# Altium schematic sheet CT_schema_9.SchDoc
size 250 x 169 mm
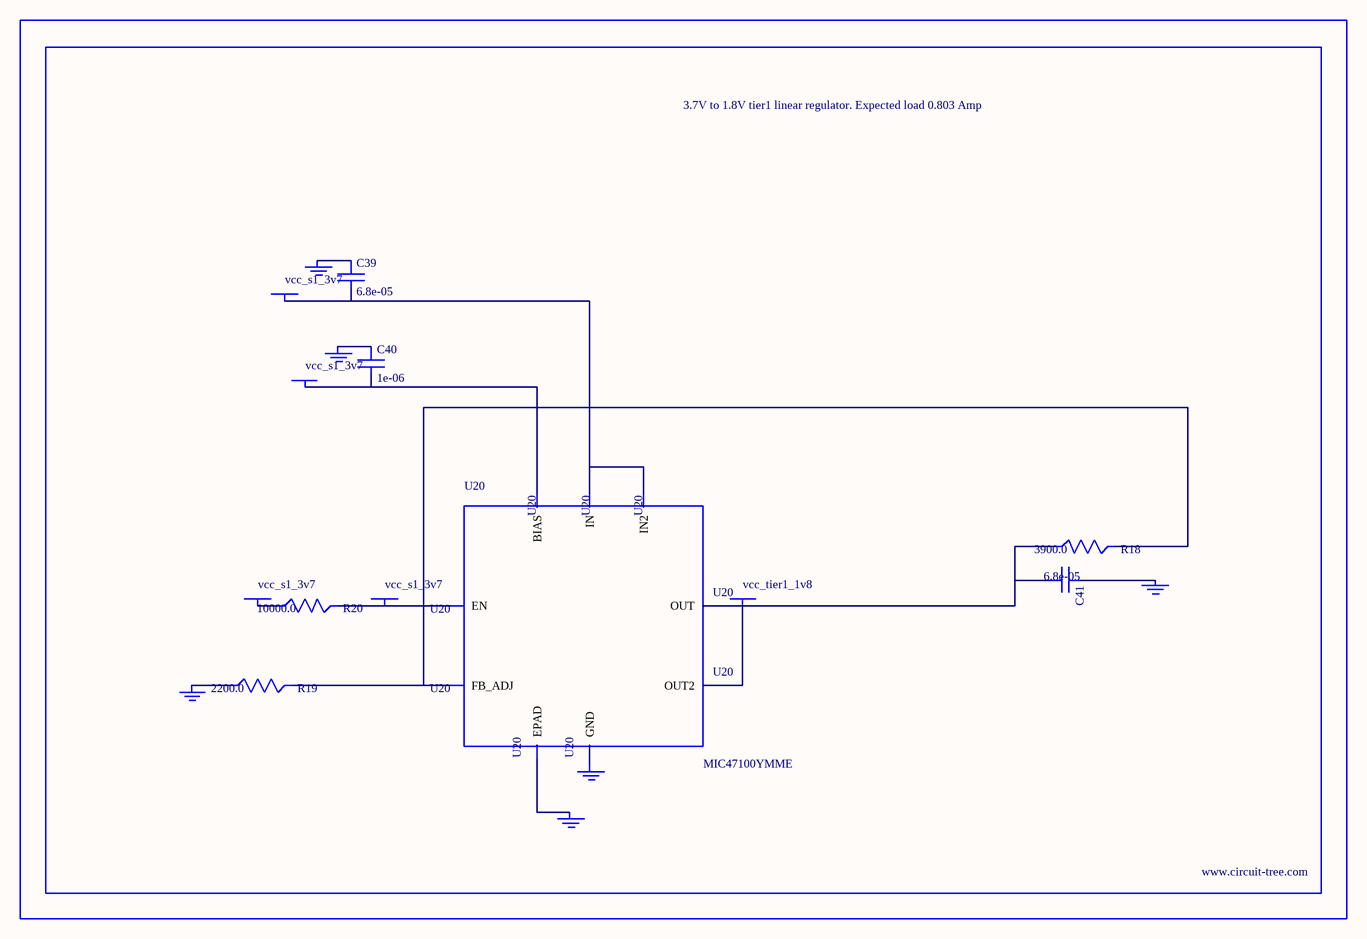
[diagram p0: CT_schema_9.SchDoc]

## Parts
BORDER8  (no value)
C39  6.8e-05  [2220]
C40  1e-06  [C0603]
C41  6.8e-05  [2220]
GND_INSTANCE_8_0  (no value)
GND_INSTANCE_8_1  (no value)
GND_INSTANCE_8_2  (no value)
GND_INSTANCE_8_3  (no value)
GND_INSTANCE_8_4  (no value)
GND_INSTANCE_8_5  (no value)
POWER_INSTANCE_8_0  vcc_s1_3v7
POWER_INSTANCE_8_1  vcc_s1_3v7
POWER_INSTANCE_8_2  vcc_s1_3v7
POWER_INSTANCE_8_3  vcc_s1_3v7
POWER_INSTANCE_8_4  vcc_tier1_1v8
R18  3900.0  [R0603]
R19  2200.0  [R0603]
R20  10000.0  [R0603]
U20  MIC47100YMME  [MSOP-8_EP]

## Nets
NetC39_1: C39.1 GND_INSTANCE_8_0.0(GND)
NetC39_2: C39.2 POWER_INSTANCE_8_0.0(PWR) U20.1(IN) U20.2(IN2)
NetC40_1: C40.1 GND_INSTANCE_8_1.0(GND)
NetC40_2: C40.2 POWER_INSTANCE_8_1.0(PWR) U20.4(BIAS)
NetC41_1: C41.1 GND_INSTANCE_8_3.0(GND)
NetC41_2: C41.2 POWER_INSTANCE_8_4.0(PWR) R18.1 U20.7(OUT) U20.8(OUT2)
NetGND_INSTANCE_8_2_0: GND_INSTANCE_8_2.0(GND) R19.1
NetGND_INSTANCE_8_4_0: GND_INSTANCE_8_4.0(GND) U20.EPAD
NetGND_INSTANCE_8_5_0: GND_INSTANCE_8_5.0(GND) U20.3(GND)
NetPOWER_INSTANCE_8_2_0: POWER_INSTANCE_8_2.0(PWR) R20.1
NetPOWER_INSTANCE_8_3_0: POWER_INSTANCE_8_3.0(PWR) R20.2 U20.5(EN)
NetR18_2: R18.2 R19.2 U20.6(FB_ADJ)

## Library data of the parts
BORDER8 = BORDER_PAGE8
C39 C41 = C5750X5R1A686M
C40 = C0603C105K3RACTU
GND_INSTANCE_8_0-GND_INSTANCE_8_5 = GND
POWER_INSTANCE_8_0-POWER_INSTANCE_8_4 = PWR
R18 = RC0603JR-073K9L
R19 = RC0603JR-072K2L
R20 = RC0603JR-0710KL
